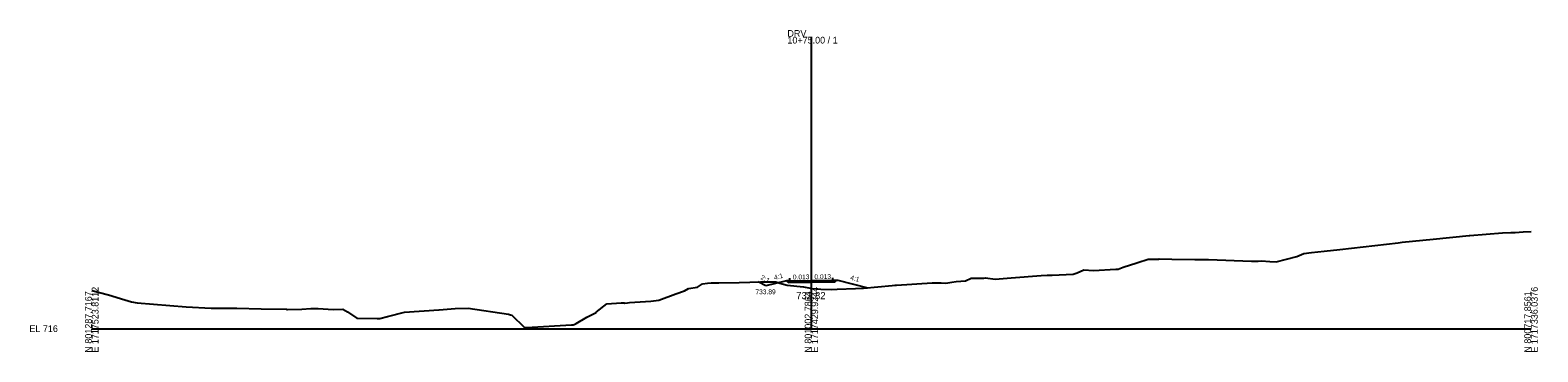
# Model space of a CAD drawing. Extents: x -26 to 603, y -10 to 3134.
# Drawn here: x -26 to 603, y 1490 to 1625 of the extents above; entities that cross this region are included whole.
import ezdxf

# ---------------------------------------------------------------- set-up
doc = ezdxf.new("R2010")
doc.units = 0
for name, color, linetype in [('Exist Cross Section Cell', 7, 'Continuous'), ('Exist XS Center Line Elevation Label', 7, 'Continuous'), ('Exist XS Ground Line', 7, 'Continuous'), ('Prop XS Ditch Slope Text', 7, 'Continuous'), ('Prop XS Ditch Standard Text', 7, 'Continuous'), ('Prop XS Dump Level', 7, 'Continuous'), ('Prop XS EOT Tick Mark', 7, 'Continuous'), ('Prop XS Finish Grade', 7, 'Continuous'), ('Prop XS Finish Grade Earthwork', 7, 'Continuous'), ('Prop XS Finish Grade Pavement', 7, 'Continuous'), ('Prop XS Pvmt Edge Slope', 7, 'Continuous'), ('Prop XS SE Text', 7, 'Continuous'), ('Prop XS Side Slope Text', 7, 'Continuous'), ('Prop XS Subgrade Earthwork', 7, 'Continuous')]:
    doc.layers.add(name, color=color, linetype=linetype)

msp = doc.modelspace()

# ---------------------------------------------------------------- linework, layer by layer
at = {"layer": 'Exist Cross Section Cell'}
for p, q in [((300, 1500), (300, 1621.87)), ((0, 1500), (300, 1500)), ((300, 1500), (600, 1500))]:
    msp.add_line(p, q, dxfattribs=at)
at = {"layer": 'Exist XS Ground Line'}
for p, q in [((574.45, 1538.97), (588.06, 1540.04)), ((588.06, 1540.04), (591.55, 1540.13)), ((591.55, 1540.13), (593.37, 1540.23)), ((593.37, 1540.23), (596.73, 1540.42)), ((596.73, 1540.42), (600, 1540.62)), ((520.35, 1533.07), (544.59, 1535.91)), ((544.59, 1535.91), (545.46, 1536)), ((545.46, 1536), (546.23, 1536.08)), ((546.23, 1536.08), (559.25, 1537.44)), ((559.25, 1537.44), (574.17, 1538.94)), ((574.17, 1538.94), (574.28, 1538.95)), ((574.28, 1538.95), (574.39, 1538.96)), ((574.39, 1538.96), (574.45, 1538.97)), ((430.03, 1525.66), (435.67, 1527.52)), ((435.67, 1527.52), (436.14, 1527.59)), ((436.14, 1527.59), (440.39, 1529.03)), ((440.39, 1529.03), (440.51, 1529.06)), ((440.51, 1529.06), (444.7, 1529.06)), ((444.7, 1529.06), (445.04, 1529.13)), ((445.04, 1529.13), (450.3, 1529.05)), ((450.3, 1529.05), (459.82, 1528.9)), ((459.82, 1528.9), (461.44, 1528.83)), ((461.44, 1528.83), (461.94, 1528.88)), ((461.94, 1528.88), (465.48, 1528.92)), ((465.48, 1528.92), (483.43, 1528.21)), ((483.43, 1528.21), (486.19, 1528.2)), ((486.19, 1528.2), (487.66, 1528.28)), ((487.66, 1528.28), (491.1, 1528.1)), ((491.1, 1528.1), (493.77, 1527.88)), ((493.77, 1527.88), (502.33, 1530.14)), ((502.33, 1530.14), (505.33, 1531.35)), ((505.33, 1531.35), (508.43, 1531.77)), ((508.43, 1531.77), (513.7, 1532.35)), ((513.7, 1532.35), (520.35, 1533.07)), ((366.64, 1521.05), (371.88, 1521.05)), ((371.88, 1521.05), (372.61, 1521.21)), ((372.61, 1521.21), (376.54, 1520.68)), ((376.54, 1520.68), (383.25, 1521.25)), ((383.25, 1521.25), (395.79, 1522.22)), ((395.79, 1522.22), (398.35, 1522.41)), ((398.35, 1522.41), (400.43, 1522.41)), ((400.43, 1522.41), (409.14, 1522.81)), ((409.14, 1522.81), (410.77, 1523.28)), ((410.77, 1523.28), (413.63, 1524.54)), ((413.63, 1524.54), (417.66, 1524.27)), ((417.66, 1524.27), (426.85, 1524.82)), ((426.85, 1524.82), (427.9, 1524.9)), ((427.9, 1524.9), (430.03, 1525.66)), ((0, 1516), (6.92, 1514.17)), ((243.45, 1514.62), (247.09, 1515.86)), ((247.09, 1515.86), (248.71, 1516.72)), ((248.71, 1516.72), (252.45, 1517.38)), ((252.45, 1517.38), (254.55, 1518.69)), ((254.55, 1518.69), (256.66, 1518.95)), ((256.66, 1518.95), (258.25, 1519.13)), ((258.25, 1519.13), (260.19, 1519.14)), ((260.19, 1519.14), (261.42, 1519.17)), ((261.42, 1519.17), (269.89, 1519.33)), ((269.89, 1519.33), (278.74, 1519.53)), ((278.74, 1519.53), (279.18, 1519.54)), ((279.18, 1519.54), (279.72, 1519.55)), ((279.72, 1519.55), (281.16, 1519.57)), ((281.16, 1519.57), (285.18, 1519.6)), ((285.18, 1519.6), (286.86, 1518.99)), ((286.86, 1518.99), (289.86, 1518.11)), ((289.86, 1518.11), (296.75, 1517.44)), ((296.75, 1517.44), (299.69, 1516.85)), ((299.69, 1516.85), (300, 1516.82)), ((300, 1516.82), (303.99, 1516.46)), ((303.99, 1516.46), (308.54, 1516.42)), ((308.54, 1516.42), (310.67, 1516.53)), ((310.67, 1516.53), (318.32, 1516.74)), ((318.32, 1516.74), (321.74, 1516.89)), ((321.74, 1516.89), (333.66, 1518.05)), ((333.66, 1518.05), (334.82, 1518.16)), ((334.82, 1518.16), (335.45, 1518.22)), ((335.45, 1518.22), (350.37, 1519.09)), ((350.37, 1519.09), (354.14, 1519.09)), ((354.14, 1519.09), (355.99, 1519.02)), ((355.99, 1519.02), (358.6, 1519.39)), ((358.6, 1519.39), (360.38, 1519.73)), ((360.38, 1519.73), (364.21, 1520.01)), ((364.21, 1520.01), (366.64, 1521.05)), ((6.92, 1514.17), (13.82, 1512)), ((13.82, 1512), (16.59, 1511.27)), ((16.59, 1511.27), (18.87, 1510.77)), ((18.87, 1510.77), (39.41, 1509.09)), ((39.41, 1509.09), (49.76, 1508.51)), ((49.76, 1508.51), (60.46, 1508.51)), ((60.46, 1508.51), (70.61, 1508.3)), ((151.43, 1508.41), (156.97, 1508.58)), ((156.97, 1508.58), (173.79, 1506.07)), ((210.29, 1506.86), (214.68, 1510.37)), ((214.68, 1510.37), (220.73, 1510.76)), ((220.73, 1510.76), (221.91, 1510.76)), ((221.91, 1510.76), (222.23, 1510.65)), ((222.23, 1510.65), (223.31, 1510.77)), ((223.31, 1510.77), (224.18, 1510.88)), ((224.18, 1510.88), (233.01, 1511.44)), ((233.01, 1511.44), (236.34, 1511.96)), ((236.34, 1511.96), (243.45, 1514.62)), ((70.61, 1508.3), (81.19, 1508.08)), ((81.19, 1508.08), (81.52, 1508.07)), ((81.52, 1508.07), (81.58, 1508.07)), ((81.58, 1508.07), (87.58, 1508.21)), ((87.58, 1508.21), (91.25, 1508.4)), ((91.25, 1508.4), (94.33, 1508.36)), ((94.33, 1508.36), (100.61, 1508.04)), ((100.61, 1508.04), (104.59, 1508.18)), ((104.59, 1508.18), (104.61, 1508.18)), ((104.61, 1508.18), (106.54, 1507.04)), ((106.54, 1507.04), (110.47, 1504.33)), ((110.47, 1504.33), (118.91, 1504.3)), ((118.91, 1504.3), (120.03, 1504.28)), ((120.03, 1504.28), (123.28, 1505.07)), ((123.28, 1505.07), (130.36, 1506.88)), ((130.36, 1506.88), (144.73, 1507.87)), ((144.73, 1507.87), (144.74, 1507.87)), ((144.74, 1507.87), (144.76, 1507.87)), ((144.76, 1507.87), (151.43, 1508.41)), ((173.79, 1506.07), (174.53, 1505.83)), ((174.53, 1505.83), (175.05, 1505.6)), ((175.05, 1505.6), (180.21, 1500.65)), ((201.93, 1502.18), (206.41, 1504.74)), ((206.41, 1504.74), (210.21, 1506.79)), ((210.21, 1506.79), (210.29, 1506.86)), ((180.21, 1500.65), (181.26, 1500.52)), ((181.26, 1500.52), (200.01, 1501.54)), ((200.01, 1501.54), (200.64, 1501.63)), ((200.64, 1501.63), (201.03, 1501.81)), ((201.03, 1501.81), (201.37, 1501.94)), ((201.37, 1501.94), (201.93, 1502.18))]:
    msp.add_line(p, q, dxfattribs=at)
at = {"layer": 'Prop XS Dump Level'}
for p, q in [((291, 1520.04), (300, 1520.16)), ((300, 1520.16), (309, 1520.28))]:
    msp.add_line(p, q, dxfattribs=at)
at = {"layer": 'Prop XS EOT Tick Mark'}
for p, q in [((309, 1520.28), (309, 1521.28)), ((291, 1520.04), (291, 1521.04))]:
    msp.add_line(p, q, dxfattribs=at)
at = {"layer": 'Prop XS Finish Grade'}
for p, q in [((291, 1520.04), (289.66, 1519.94)), ((309, 1520.28), (310.34, 1520.22))]:
    msp.add_line(p, q, dxfattribs=at)
at = {"layer": 'Prop XS Finish Grade Earthwork'}
for p, q in [((281, 1517.89), (277.78, 1519.51)), ((289, 1519.89), (281, 1517.89)), ((289.66, 1519.94), (289, 1519.89)), ((310.34, 1520.22), (311, 1520.19)), ((311, 1520.19), (323.5, 1517.06))]:
    msp.add_line(p, q, dxfattribs=at)
at = {"layer": 'Prop XS Finish Grade Pavement'}
for p, q in [((291, 1520.04), (300, 1520.16)), ((300, 1520.16), (309, 1520.28))]:
    msp.add_line(p, q, dxfattribs=at)
at = {"layer": 'Prop XS Pvmt Edge Slope'}
for p, q in [((291, 1520.04), (290.28, 1519.32)), ((309, 1520.28), (309.7, 1519.58))]:
    msp.add_line(p, q, dxfattribs=at)
at = {"layer": 'Prop XS Subgrade Earthwork'}
for p, q in [((290.28, 1519.32), (289.66, 1519.94)), ((290.28, 1519.32), (300, 1519.45)), ((300, 1519.45), (309.7, 1519.58)), ((309.7, 1519.58), (310.34, 1520.22))]:
    msp.add_line(p, q, dxfattribs=at)

# ---------------------------------------------------------------- texts
at = {"layer": 'Exist Cross Section Cell'}
for s, p in [('10+75.00 / 1', (290, 1619.07)), ('DRV', (290, 1621.87)), ('EL 716', (-26, 1498.6))]:
    msp.add_text(s, height=2.8, dxfattribs=at).set_placement(p)
for s, p in [('N 801287.7167', (0, 1490)), ('E 1717523.8112', (2.8, 1490)), ('N 801002.7864', (300, 1490)), ('E 1717429.9244', (302.8, 1490)), ('N 800717.8561', (600, 1490)), ('E 1717336.0376', (602.8, 1490))]:
    msp.add_text(s, height=2.8, rotation=90, dxfattribs=at).set_placement(p)
at = {"layer": 'Exist XS Center Line Elevation Label'}
msp.add_text('732.82', height=3, dxfattribs=at).set_placement((293.66, 1512.32))
at = {"layer": 'Prop XS Ditch Slope Text'}
msp.add_text('4:1', height=2, rotation=14.03624, dxfattribs=at).set_placement((284.64, 1520.35))
at = {"layer": 'Prop XS Ditch Standard Text'}
msp.add_text('733.89', height=2, dxfattribs=at).set_placement((276.67, 1514.39))
at = {"layer": 'Prop XS Dump Level'}
for p in [(289, 1519.85), (311, 1520.15)]:
    msp.add_text('Case1', height=0.04, dxfattribs=at).set_placement(p)
at = {"layer": 'Prop XS SE Text'}
for p in [(292.27, 1520.56), (301.27, 1520.68)]:
    msp.add_text('0.013', height=2, rotation=0.7639, dxfattribs=at).set_placement(p)
at = {"layer": 'Prop XS Side Slope Text'}
for s, rotation, p in [('2:1', 333.43495, (278.61, 1520.76)), ('4:1', 345.96376, (316.05, 1520.47))]:
    msp.add_text(s, height=2, rotation=rotation, dxfattribs=at).set_placement(p)

doc.saveas('drawing.dxf')
